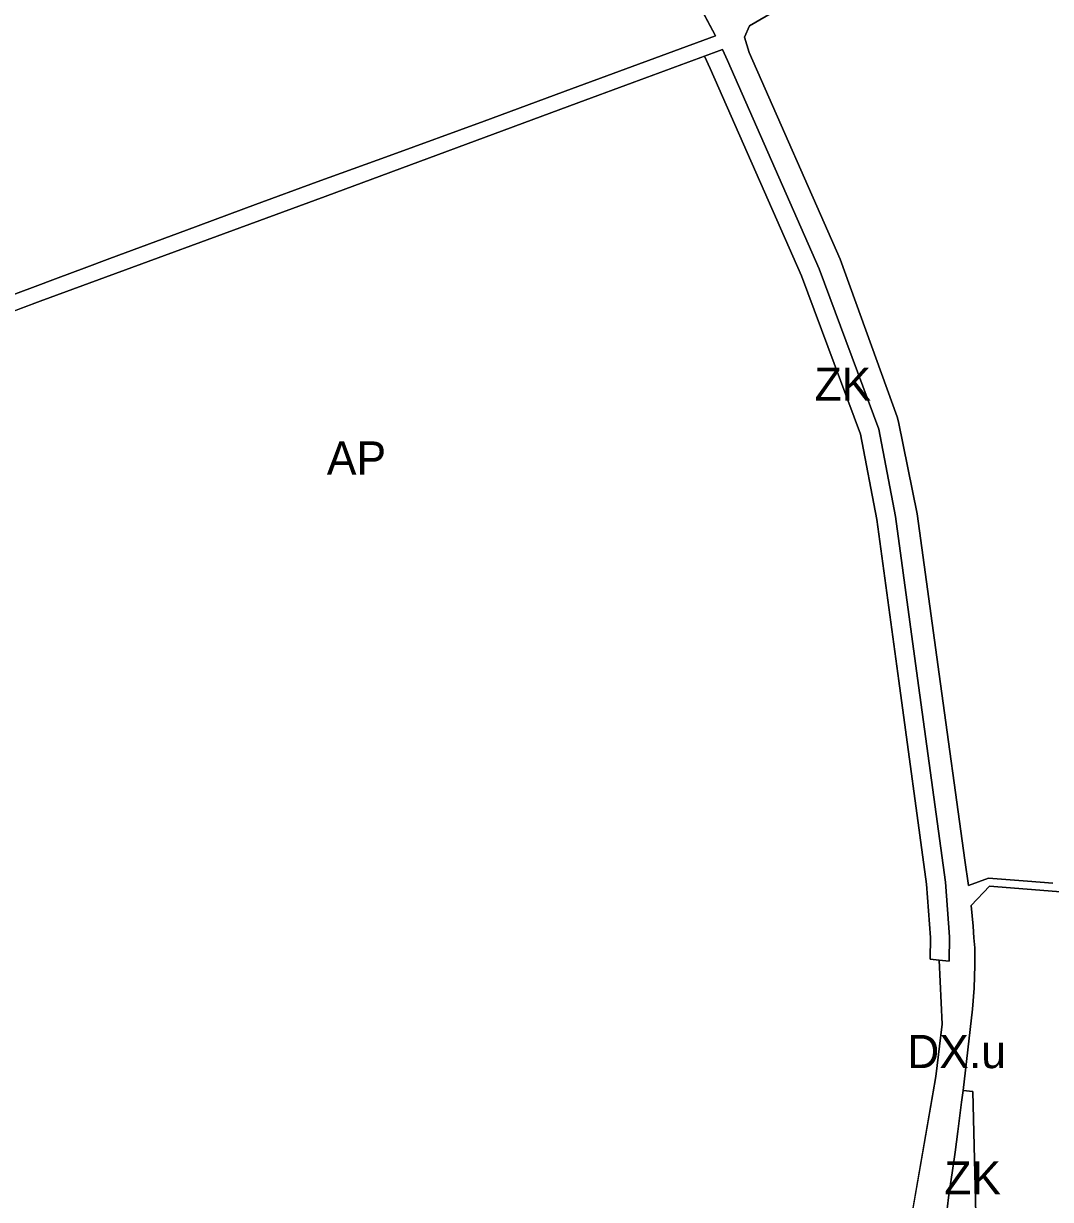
# Model space of a CAD drawing. Extents: x -555509 to -553005, y -1186756 to -1182560.
# Drawn here: x -554517.6 to -554084.6, y -1184039.1 to -1183543.6 of the extents above; entities that cross this region are included whole.
import ezdxf

# ---------------------------------------------------------------- set-up
doc = ezdxf.new("R2010")
doc.units = 0
for name, color, linetype in [('Level 26', 7, 'Continuous'), ('Level 59', 7, 'Continuous'), ('OBRYS_PLOCH', 7, 'Continuous'), ('stav_AP', 7, 'Continuous'), ('stav_ZK', 7, 'Continuous')]:
    doc.layers.add(name, color=color, linetype=linetype)

msp = doc.modelspace()

# ---------------------------------------------------------------- linework, layer by layer
at = {"layer": 'Level 26'}
for p, q in [((-554257.71, -1183488.58), (-554225.85, -1183548.82)), ((-554211.53, -1183544.58), (-554194.78, -1183534.92)), ((-554213.69, -1183549.26), (-554211.53, -1183544.58)), ((-554225.85, -1183548.82), (-554286.57, -1183571.14)), ((-554211.72, -1183555.74), (-554213.69, -1183549.26)), ((-554283.44, -1183576.79), (-554222.96, -1183554.52)), ((-554222.96, -1183554.52), (-554220.83, -1183559.18)), ((-554173.28, -1183642.94), (-554211.72, -1183555.74)), ((-554220.83, -1183559.18), (-554182.11, -1183646.91)), ((-554286.57, -1183571.14), (-554323.44, -1183584.68)), ((-554390.4, -1183616.42), (-554283.44, -1183576.79)), ((-554323.44, -1183584.68), (-554363.38, -1183599.28)), ((-554363.38, -1183599.28), (-554393.73, -1183610.29)), ((-554393.73, -1183610.29), (-554419.73, -1183619.89)), ((-554510.52, -1183660.58), (-554390.4, -1183616.42)), ((-554419.73, -1183619.89), (-554448.84, -1183630.65)), ((-554448.84, -1183630.65), (-554481.24, -1183642.52)), ((-554481.24, -1183642.52), (-554492.09, -1183646.61)), ((-554149.22, -1183709.32), (-554173.28, -1183642.94)), ((-554502.93, -1183650.7), (-554513.78, -1183654.8)), ((-554492.09, -1183646.61), (-554502.93, -1183650.7)), ((-554182.11, -1183646.91), (-554157.03, -1183714.44)), ((-554513.78, -1183654.8), (-554546.94, -1183667.09)), ((-554633.18, -1183706.01), (-554510.52, -1183660.58)), ((-554148.72, -1183711.35), (-554149.22, -1183709.32)), ((-554157.03, -1183714.44), (-554149.99, -1183751.32)), ((-554140.77, -1183750.23), (-554148.72, -1183711.35)), ((-554131.6, -1183817.78), (-554140.77, -1183750.23)), ((-554149.99, -1183751.32), (-554140.62, -1183819.44)), ((-554140.62, -1183819.44), (-554128.95, -1183905.34)), ((-554120.73, -1183896.07), (-554131.6, -1183817.78)), ((-554119.19, -1183906.77), (-554120.73, -1183896.07)), ((-554110.69, -1183903.74), (-554119.19, -1183906.77)), ((-554094.26, -1183904.9), (-554110.69, -1183903.74)), ((-554128.95, -1183905.34), (-554127.22, -1183928.43)), ((-554083.69, -1183905.82), (-554094.26, -1183904.9)), ((-554127.22, -1183928.43), (-554127.39, -1183938.69)), ((-554116.48, -1183940.32), (-554116.51, -1183933.1)), ((-554127.39, -1183938.69), (-554131.55, -1183938.27)), ((-554131.55, -1183938.27), (-554130.35, -1183965.16)), ((-554130.35, -1183965.16), (-554132.91, -1183987.28)), ((-554132.91, -1183987.28), (-554144.11, -1184051.59)), ((-554126.05, -1184027.85), (-554124.86, -1184019.2)), ((-554127.5, -1184037.16), (-554126.05, -1184027.85)), ((-554130.79, -1184065.34), (-554127.5, -1184037.16))]:
    msp.add_line(p, q, dxfattribs=at)
for points in [[(-554118.07, -1183915.18), (-554110.39, -1183907.02), (-554046.81, -1183912.08), (-554005.63, -1183918.73), (-553956.98, -1183929.73), (-553899.51, -1183948.08), (-553812.95, -1183975.4)], [(-554116.51, -1183933.1), (-554116.98, -1183928.82), (-554117.19, -1183923.95), (-554118.07, -1183915.18)], [(-554122.1, -1183998.07), (-554121.45, -1183993.16), (-554119.49, -1183976.07), (-554117.53, -1183958.93), (-554116.86, -1183950), (-554116.48, -1183940.32)], [(-554124.86, -1184019.2), (-554123.72, -1184010.4), (-554122.1, -1183998.07)]]:
    msp.add_lwpolyline(points, dxfattribs=at)
at = {"layer": 'OBRYS_PLOCH'}
for p, q in [((-554257.71, -1183488.58), (-554225.85, -1183548.82)), ((-554225.85, -1183548.82), (-554257.71, -1183488.58)), ((-554211.53, -1183544.58), (-554194.78, -1183534.92)), ((-554194.78, -1183534.92), (-554211.53, -1183544.58)), ((-554213.69, -1183549.26), (-554211.53, -1183544.58)), ((-554211.53, -1183544.58), (-554213.69, -1183549.26)), ((-554225.85, -1183548.82), (-554286.57, -1183571.14)), ((-554286.57, -1183571.14), (-554225.85, -1183548.82)), ((-554211.72, -1183555.74), (-554213.69, -1183549.26)), ((-554213.69, -1183549.26), (-554211.72, -1183555.74)), ((-554283.44, -1183576.79), (-554222.96, -1183554.52)), ((-554230.49, -1183557.29), (-554283.44, -1183576.79)), ((-554222.96, -1183554.52), (-554230.49, -1183557.29)), ((-554220.83, -1183559.18), (-554222.96, -1183554.52)), ((-554222.96, -1183554.52), (-554220.83, -1183559.18)), ((-554173.28, -1183642.94), (-554211.72, -1183555.74)), ((-554211.72, -1183555.74), (-554173.28, -1183642.94)), ((-554182.11, -1183646.91), (-554220.83, -1183559.18)), ((-554220.83, -1183559.18), (-554182.11, -1183646.91)), ((-554286.57, -1183571.14), (-554323.44, -1183584.68)), ((-554323.44, -1183584.68), (-554286.57, -1183571.14)), ((-554390.4, -1183616.42), (-554283.44, -1183576.79)), ((-554283.44, -1183576.79), (-554390.4, -1183616.42)), ((-554323.44, -1183584.68), (-554363.38, -1183599.28)), ((-554363.38, -1183599.28), (-554323.44, -1183584.68)), ((-554363.38, -1183599.28), (-554393.73, -1183610.29)), ((-554393.73, -1183610.29), (-554363.38, -1183599.28)), ((-554393.73, -1183610.29), (-554419.73, -1183619.89)), ((-554419.73, -1183619.89), (-554393.73, -1183610.29)), ((-554510.52, -1183660.58), (-554390.4, -1183616.42)), ((-554390.4, -1183616.42), (-554510.52, -1183660.58)), ((-554419.73, -1183619.89), (-554448.84, -1183630.65)), ((-554448.84, -1183630.65), (-554419.73, -1183619.89)), ((-554448.84, -1183630.65), (-554481.24, -1183642.52)), ((-554481.24, -1183642.52), (-554448.84, -1183630.65)), ((-554481.24, -1183642.52), (-554492.09, -1183646.61)), ((-554492.09, -1183646.61), (-554481.24, -1183642.52)), ((-554149.22, -1183709.32), (-554173.28, -1183642.94)), ((-554173.28, -1183642.94), (-554149.22, -1183709.32)), ((-554502.93, -1183650.7), (-554513.78, -1183654.8)), ((-554513.78, -1183654.8), (-554502.93, -1183650.7)), ((-554492.09, -1183646.61), (-554502.93, -1183650.7)), ((-554502.93, -1183650.7), (-554492.09, -1183646.61)), ((-554157.03, -1183714.44), (-554182.11, -1183646.91)), ((-554182.11, -1183646.91), (-554157.03, -1183714.44)), ((-554513.78, -1183654.8), (-554546.94, -1183667.09)), ((-554546.94, -1183667.09), (-554513.78, -1183654.8)), ((-554633.18, -1183706.01), (-554510.52, -1183660.58)), ((-554510.52, -1183660.58), (-554633.18, -1183706.01)), ((-554148.72, -1183711.35), (-554149.22, -1183709.32)), ((-554149.22, -1183709.32), (-554148.72, -1183711.35)), ((-554149.99, -1183751.32), (-554157.03, -1183714.44)), ((-554157.03, -1183714.44), (-554149.99, -1183751.32)), ((-554140.77, -1183750.23), (-554148.72, -1183711.35)), ((-554148.72, -1183711.35), (-554140.77, -1183750.23)), ((-554131.6, -1183817.78), (-554140.77, -1183750.23)), ((-554140.77, -1183750.23), (-554131.6, -1183817.78)), ((-554140.62, -1183819.44), (-554149.99, -1183751.32)), ((-554149.99, -1183751.32), (-554140.62, -1183819.44)), ((-554128.95, -1183905.34), (-554140.62, -1183819.44)), ((-554140.62, -1183819.44), (-554128.95, -1183905.34)), ((-554120.73, -1183896.07), (-554131.6, -1183817.78)), ((-554131.6, -1183817.78), (-554120.73, -1183896.07)), ((-554119.19, -1183906.77), (-554120.73, -1183896.07)), ((-554120.73, -1183896.07), (-554119.19, -1183906.77)), ((-554110.69, -1183903.74), (-554119.19, -1183906.77)), ((-554119.19, -1183906.77), (-554110.69, -1183903.74)), ((-554094.26, -1183904.9), (-554110.69, -1183903.74)), ((-554110.69, -1183903.74), (-554094.26, -1183904.9)), ((-554128.95, -1183905.34), (-554127.22, -1183928.43)), ((-554083.69, -1183905.82), (-554094.26, -1183904.9)), ((-554094.26, -1183904.9), (-554083.69, -1183905.82)), ((-554127.22, -1183928.43), (-554127.39, -1183938.69)), ((-554116.48, -1183940.32), (-554116.51, -1183933.1)), ((-554116.51, -1183933.1), (-554116.48, -1183940.32)), ((-554135.38, -1183937.86), (-554131.55, -1183938.27)), ((-554131.55, -1183938.27), (-554127.39, -1183938.69)), ((-554127.39, -1183938.69), (-554131.55, -1183938.27)), ((-554131.55, -1183938.27), (-554130.35, -1183965.16)), ((-554130.35, -1183965.16), (-554132.91, -1183987.28)), ((-554132.91, -1183987.28), (-554144.11, -1184051.59)), ((-554126.05, -1184027.85), (-554124.86, -1184019.2)), ((-554127.5, -1184037.16), (-554126.05, -1184027.85)), ((-554130.79, -1184065.34), (-554127.5, -1184037.16))]:
    msp.add_line(p, q, dxfattribs=at)
for points in [[(-554230.49, -1183557.29), (-554228.13, -1183562.46), (-554189.53, -1183649.92), (-554164.76, -1183716.6)], [(-554164.76, -1183716.6), (-554189.53, -1183649.92), (-554228.13, -1183562.46), (-554230.49, -1183557.29)], [(-554164.76, -1183716.6), (-554157.89, -1183752.62), (-554148.55, -1183820.52), (-554136.91, -1183906.18), (-554135.22, -1183928.66), (-554135.38, -1183937.86)], [(-554135.38, -1183937.86), (-554135.22, -1183928.66), (-554136.91, -1183906.18), (-554148.55, -1183820.52), (-554157.89, -1183752.62), (-554164.76, -1183716.6)], [(-554127.39, -1183938.69), (-554127.22, -1183928.43), (-554128.95, -1183905.34)], [(-554118.07, -1183915.18), (-554110.39, -1183907.02), (-554046.81, -1183912.08), (-554005.63, -1183918.73), (-553956.98, -1183929.73), (-553899.51, -1183948.08), (-553812.95, -1183975.4)], [(-553812.95, -1183975.4), (-553899.51, -1183948.08), (-553956.98, -1183929.73), (-554005.63, -1183918.73), (-554046.81, -1183912.08), (-554110.39, -1183907.02), (-554118.07, -1183915.18)], [(-554116.51, -1183933.1), (-554116.98, -1183928.82), (-554117.19, -1183923.95), (-554118.07, -1183915.18)], [(-554118.07, -1183915.18), (-554117.19, -1183923.95), (-554116.98, -1183928.82), (-554116.51, -1183933.1)], [(-554165.91, -1184122.25), (-554150.8, -1184126.62), (-554147.33, -1184087.16), (-554144.11, -1184051.59), (-554132.91, -1183987.28), (-554130.35, -1183965.16), (-554131.55, -1183938.27), (-554135.38, -1183937.86)], [(-554122.1, -1183998.07), (-554121.45, -1183993.16), (-554119.49, -1183976.07), (-554117.53, -1183958.93), (-554116.86, -1183950), (-554116.48, -1183940.32)], [(-554116.48, -1183940.32), (-554116.86, -1183950), (-554117.53, -1183958.93), (-554119.49, -1183976.07), (-554121.45, -1183993.16)], [(-554115.59, -1184068.14), (-554117.34, -1183993.61), (-554121.45, -1183993.16), (-554122.1, -1183998.07), (-554123.72, -1184010.4), (-554124.86, -1184019.2), (-554126.05, -1184027.85), (-554127.5, -1184037.16), (-554130.79, -1184065.34), (-554127.06, -1184066.03), (-554115.59, -1184068.14)], [(-554121.45, -1183993.16), (-554117.34, -1183993.61), (-554115.59, -1184068.14)], [(-554124.86, -1184019.2), (-554123.72, -1184010.4), (-554122.1, -1183998.07)]]:
    msp.add_lwpolyline(points, dxfattribs=at)
at = {"layer": 'stav_AP'}
for p, q in [((-554225.85, -1183548.82), (-554257.71, -1183488.58)), ((-554194.78, -1183534.92), (-554211.53, -1183544.58)), ((-554211.53, -1183544.58), (-554213.69, -1183549.26)), ((-554286.57, -1183571.14), (-554225.85, -1183548.82)), ((-554213.69, -1183549.26), (-554211.72, -1183555.74)), ((-554230.49, -1183557.29), (-554283.44, -1183576.79)), ((-554211.72, -1183555.74), (-554173.28, -1183642.94)), ((-554323.44, -1183584.68), (-554286.57, -1183571.14)), ((-554283.44, -1183576.79), (-554390.4, -1183616.42)), ((-554363.38, -1183599.28), (-554323.44, -1183584.68)), ((-554393.73, -1183610.29), (-554363.38, -1183599.28)), ((-554419.73, -1183619.89), (-554393.73, -1183610.29)), ((-554390.4, -1183616.42), (-554510.52, -1183660.58)), ((-554448.84, -1183630.65), (-554419.73, -1183619.89)), ((-554481.24, -1183642.52), (-554448.84, -1183630.65)), ((-554492.09, -1183646.61), (-554481.24, -1183642.52)), ((-554173.28, -1183642.94), (-554149.22, -1183709.32)), ((-554513.78, -1183654.8), (-554502.93, -1183650.7)), ((-554502.93, -1183650.7), (-554492.09, -1183646.61)), ((-554546.94, -1183667.09), (-554513.78, -1183654.8)), ((-554510.52, -1183660.58), (-554633.18, -1183706.01)), ((-554149.22, -1183709.32), (-554148.72, -1183711.35)), ((-554148.72, -1183711.35), (-554140.77, -1183750.23)), ((-554140.77, -1183750.23), (-554131.6, -1183817.78)), ((-554131.6, -1183817.78), (-554120.73, -1183896.07)), ((-554120.73, -1183896.07), (-554119.19, -1183906.77)), ((-554119.19, -1183906.77), (-554110.69, -1183903.74)), ((-554110.69, -1183903.74), (-554094.26, -1183904.9)), ((-554094.26, -1183904.9), (-554083.69, -1183905.82)), ((-554116.51, -1183933.1), (-554116.48, -1183940.32))]:
    msp.add_line(p, q, dxfattribs=at)
for points in [[(-554164.76, -1183716.6), (-554189.53, -1183649.92), (-554228.13, -1183562.46), (-554230.49, -1183557.29)], [(-554135.38, -1183937.86), (-554135.22, -1183928.66), (-554136.91, -1183906.18), (-554148.55, -1183820.52), (-554157.89, -1183752.62), (-554164.76, -1183716.6)], [(-553812.95, -1183975.4), (-553899.51, -1183948.08), (-553956.98, -1183929.73), (-554005.63, -1183918.73), (-554046.81, -1183912.08), (-554110.39, -1183907.02), (-554118.07, -1183915.18)], [(-554118.07, -1183915.18), (-554117.19, -1183923.95), (-554116.98, -1183928.82), (-554116.51, -1183933.1)], [(-554165.91, -1184122.25), (-554150.8, -1184126.62), (-554147.33, -1184087.16), (-554144.11, -1184051.59), (-554132.91, -1183987.28), (-554130.35, -1183965.16), (-554131.55, -1183938.27), (-554135.38, -1183937.86)], [(-554116.48, -1183940.32), (-554116.86, -1183950), (-554117.53, -1183958.93), (-554119.49, -1183976.07), (-554121.45, -1183993.16)], [(-554121.45, -1183993.16), (-554117.34, -1183993.61), (-554115.59, -1184068.14)]]:
    msp.add_lwpolyline(points, dxfattribs=at)
at = {"layer": 'stav_ZK'}
for p, q in [((-554222.96, -1183554.52), (-554230.49, -1183557.29)), ((-554220.83, -1183559.18), (-554222.96, -1183554.52)), ((-554182.11, -1183646.91), (-554220.83, -1183559.18)), ((-554157.03, -1183714.44), (-554182.11, -1183646.91)), ((-554149.99, -1183751.32), (-554157.03, -1183714.44)), ((-554140.62, -1183819.44), (-554149.99, -1183751.32)), ((-554128.95, -1183905.34), (-554140.62, -1183819.44)), ((-554135.38, -1183937.86), (-554131.55, -1183938.27)), ((-554131.55, -1183938.27), (-554127.39, -1183938.69))]:
    msp.add_line(p, q, dxfattribs=at)
for points in [[(-554230.49, -1183557.29), (-554228.13, -1183562.46), (-554189.53, -1183649.92), (-554164.76, -1183716.6)], [(-554164.76, -1183716.6), (-554157.89, -1183752.62), (-554148.55, -1183820.52), (-554136.91, -1183906.18), (-554135.22, -1183928.66), (-554135.38, -1183937.86)], [(-554127.39, -1183938.69), (-554127.22, -1183928.43), (-554128.95, -1183905.34)], [(-554115.59, -1184068.14), (-554117.34, -1183993.61), (-554121.45, -1183993.16), (-554122.1, -1183998.07), (-554123.72, -1184010.4), (-554124.86, -1184019.2), (-554126.05, -1184027.85), (-554127.5, -1184037.16), (-554130.79, -1184065.34), (-554127.06, -1184066.03), (-554115.59, -1184068.14)]]:
    msp.add_lwpolyline(points, dxfattribs=at)

# ---------------------------------------------------------------- texts
at = {"layer": 'Level 59'}
for s, p in [('ZK', (-554184.11, -1183702.56)), ('AP', (-554389.7, -1183733.66)), ('DX.u', (-554145.02, -1183983.74)), ('ZK', (-554129.38, -1184036.96))]:
    msp.add_text(s, height=14, dxfattribs=at).set_placement(p)

doc.saveas('drawing.dxf')
